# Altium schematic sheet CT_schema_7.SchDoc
size 387 x 379 mm
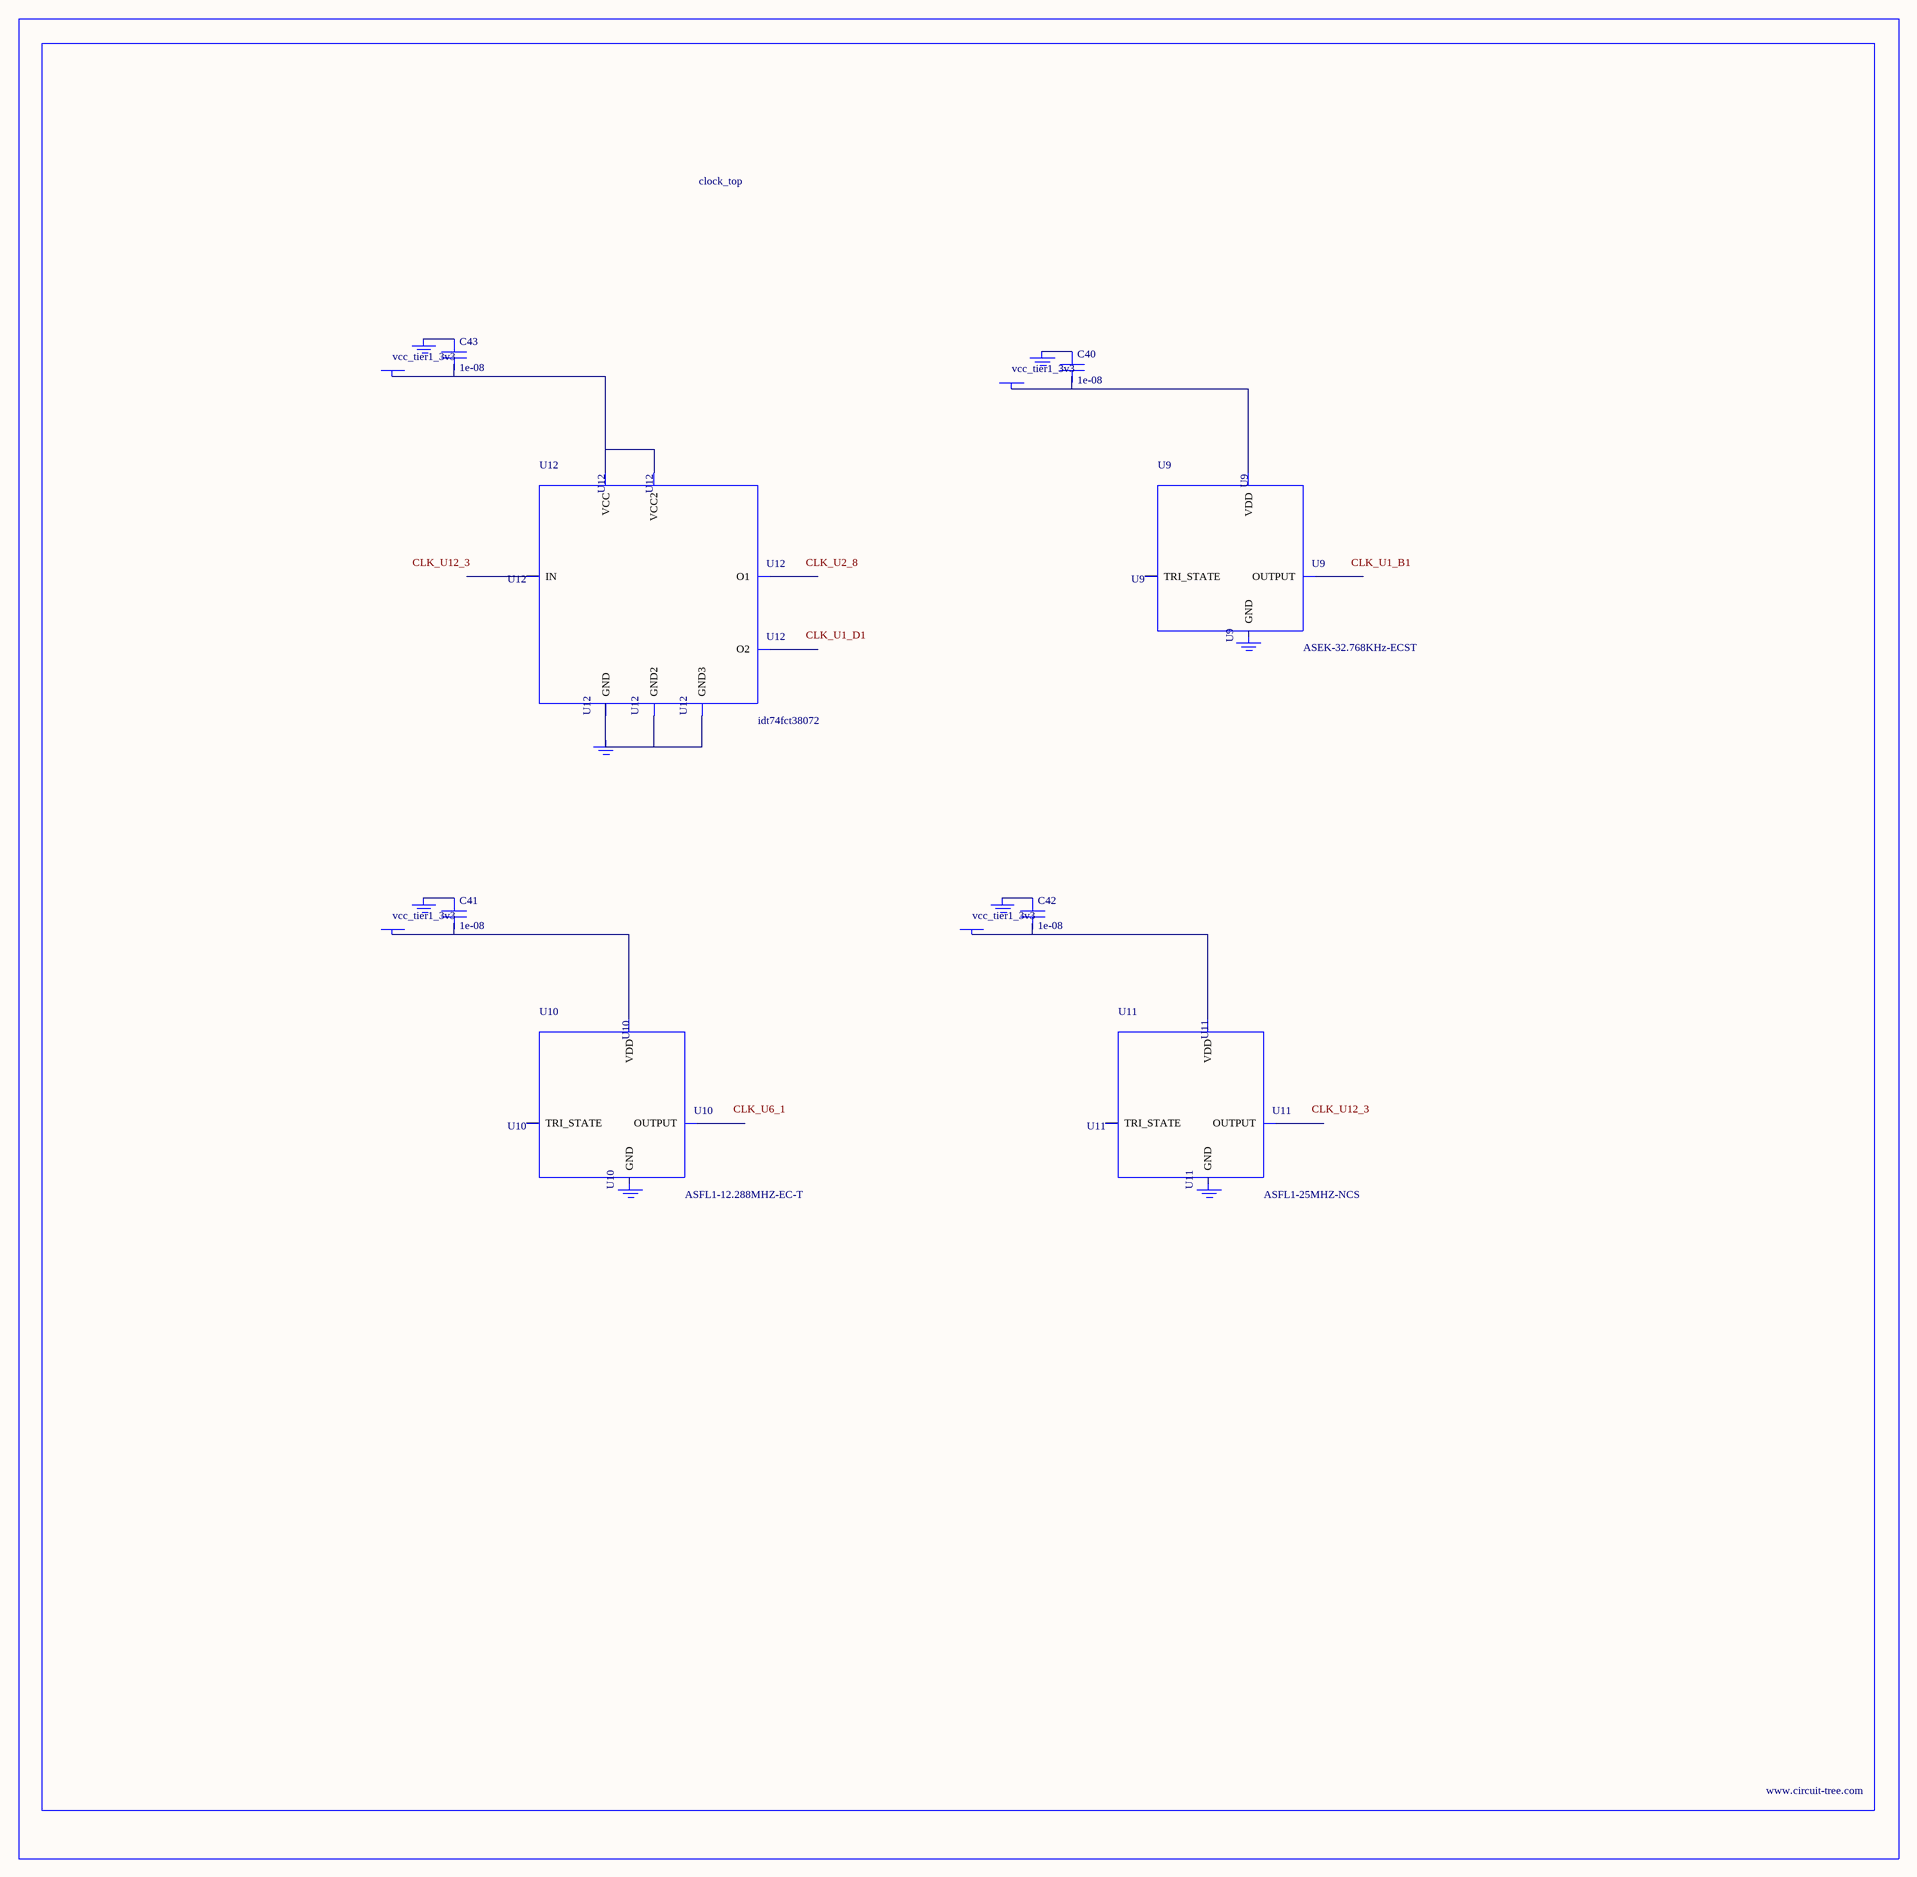
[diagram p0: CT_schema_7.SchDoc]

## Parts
BORDER6  (no value)
C40  1e-08  [C0402]
C41  1e-08  [C0402]
C42  1e-08  [C0402]
C43  1e-08  [C0402]
GND_INSTANCE_6_0  (no value)
GND_INSTANCE_6_1  (no value)
GND_INSTANCE_6_2  (no value)
GND_INSTANCE_6_3  (no value)
GND_INSTANCE_6_4  (no value)
GND_INSTANCE_6_5  (no value)
GND_INSTANCE_6_6  (no value)
GND_INSTANCE_6_7  (no value)
POWER_INSTANCE_6_0  vcc_tier1_3v3
POWER_INSTANCE_6_1  vcc_tier1_3v3
POWER_INSTANCE_6_2  vcc_tier1_3v3
POWER_INSTANCE_6_3  vcc_tier1_3v3
U9  ASEK-32.768KHz-ECST  [ASEK]
U10  ASFL1-12.288MHZ-EC-T  [ASFL1]
U11  ASFL1-25MHZ-NCS  [ASFL1]
U12  idt74fct38072  [IDT74FCT38072]

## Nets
NetC40_1: C40.1 GND_INSTANCE_6_0.0(GND)
NetC40_2: C40.2 POWER_INSTANCE_6_0.0(PWR) U9.4(VDD)
NetC41_1: C41.1 GND_INSTANCE_6_2.0(GND)
NetC41_2: C41.2 POWER_INSTANCE_6_1.0(PWR) U10.4(VDD)
NetC42_1: C42.1 GND_INSTANCE_6_4.0(GND)
NetC42_2: C42.2 POWER_INSTANCE_6_2.0(PWR) U11.4(VDD)
NetC43_1: C43.1 GND_INSTANCE_6_6.0(GND)
NetC43_2: C43.2 POWER_INSTANCE_6_3.0(PWR) U12.1(VCC) U12.2(VCC2)
NetGND_INSTANCE_6_7_0: GND_INSTANCE_6_7.0(GND) U12.4(GND) U12.5(GND2) U12.8(GND3)

Not connected (* = marked no-connect by the designer): GND_INSTANCE_6_1 0(GND); GND_INSTANCE_6_3 0(GND); GND_INSTANCE_6_5 0(GND); U9 1(TRI_STATE) 2(GND) 3(OUTPUT); U10 1(TRI_STATE) 2(GND) 3(OUTPUT); U11 1(TRI_STATE) 2(GND) 3(OUTPUT); U12 3(IN) 6(O2) 7(O1)

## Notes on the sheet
- Labels drawn without touching a wire or pin: CLK_U1_B1, CLK_U1_D1, CLK_U2_8, CLK_U6_1, CLK_U12_3

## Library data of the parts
BORDER6 = BORDER_PAGE6
C40-C43 = C0402C103K3RAC
GND_INSTANCE_6_0-GND_INSTANCE_6_7 = GND
POWER_INSTANCE_6_0-POWER_INSTANCE_6_3 = PWR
